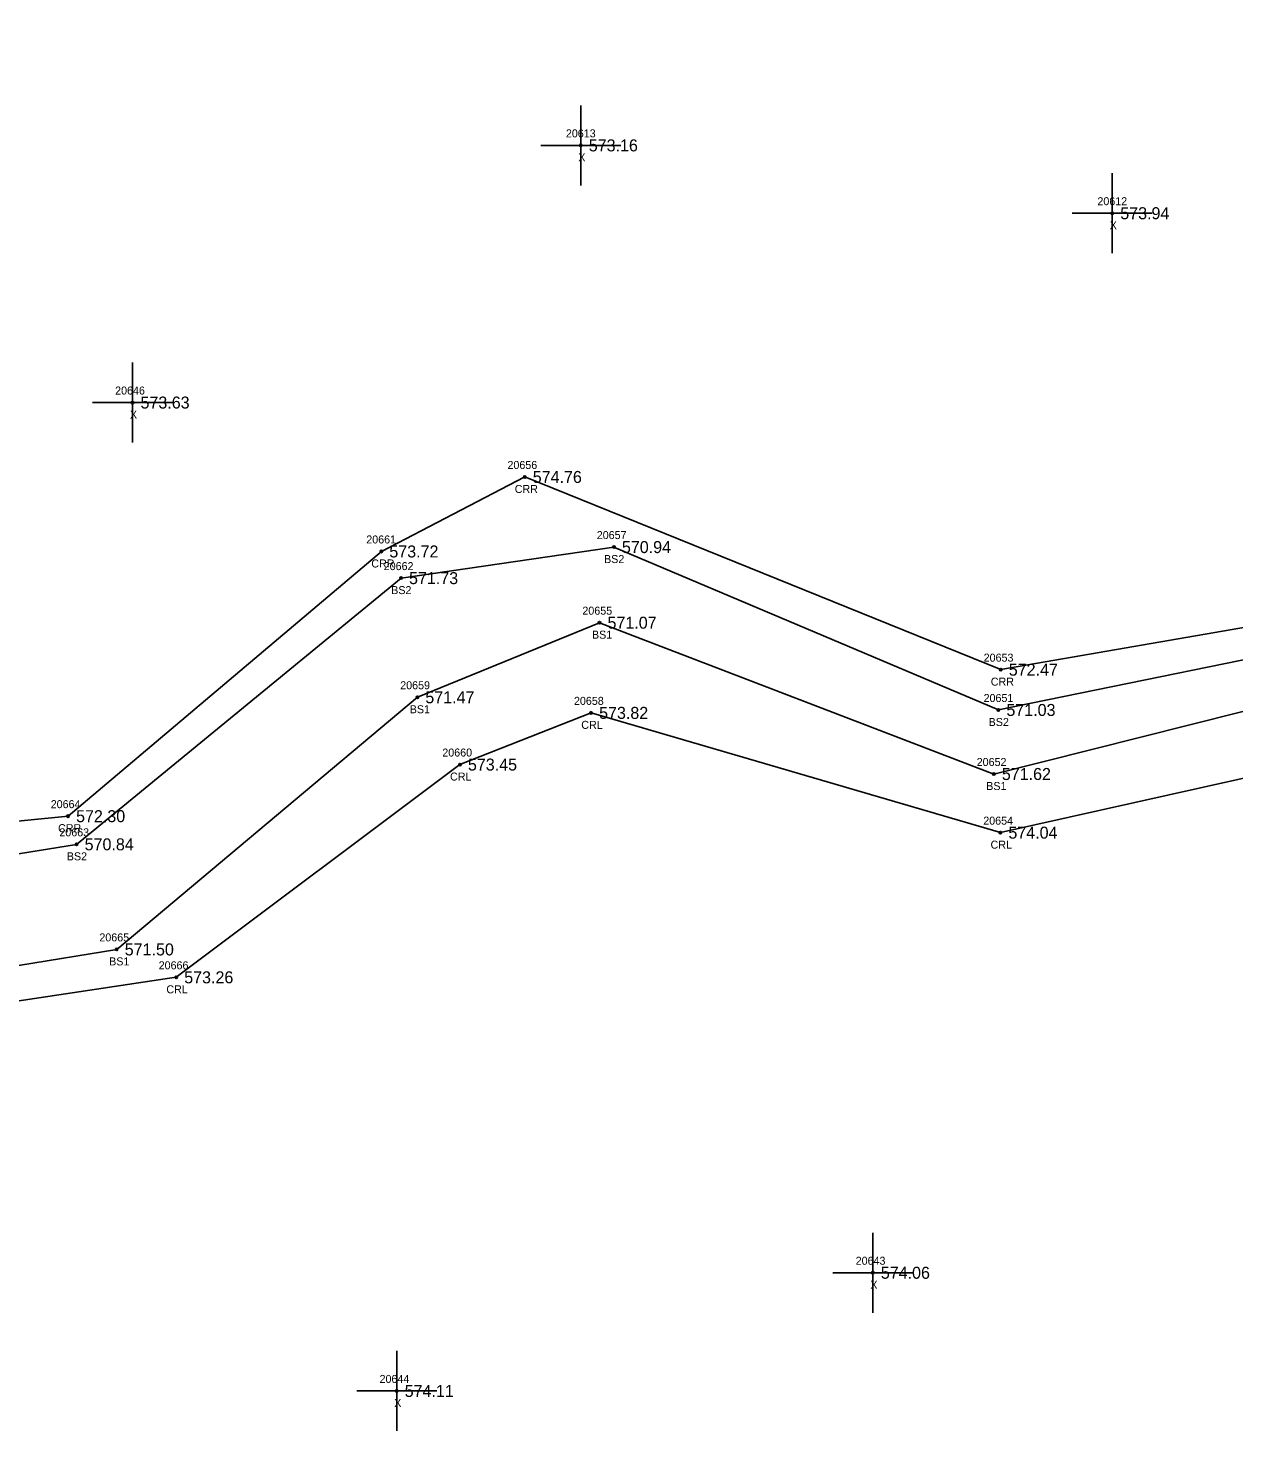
# Model space of a CAD drawing. Extents: x 1664837 to 1666270, y 987403 to 988245.
# Drawn here: x 1665162.3 to 1665313, y 987557.1 to 987732.4 of the extents above; entities that cross this region are included whole.
import ezdxf

# ---------------------------------------------------------------- set-up
doc = ezdxf.new("R2010")
doc.units = 0
for name, color, linetype in [('RD_DTM_BkLn2', 7, 'Continuous'), ('RD_DTM_BkLn_txCode', 7, 'Continuous'), ('RD_EX_H2O', 7, 'Continuous'), ('RD_EX_H2O_txCode', 7, 'Continuous'), ('RD_EX_Misc', 7, 'Continuous'), ('RD_EX_Misc_txCode', 7, 'Continuous'), ('RD_EX_TX_H2O_ELEV', 7, 'Continuous'), ('RD_EX_TX_Misc_ELEV', 7, 'Continuous'), ('RD_SMD_Locator', 7, 'Continuous')]:
    doc.layers.add(name, color=color, linetype=linetype)

msp = doc.modelspace()

# ---------------------------------------------------------------- linework, layer by layer
at = {"layer": 'RD_DTM_BkLn2'}
for points in [[(1665511.23, 987778.14), (1665500.12, 987754.08), (1665496.26, 987735.63), (1665475.45, 987718.43), (1665445.39, 987709.52), (1665428.04, 987704.31), (1665389.45, 987688.17), (1665361.39, 987673.13), (1665330.12, 987656.7), (1665283.57, 987647.17), (1665235.53, 987667.53), (1665208.93, 987663.65), (1665168.4, 987630.38), (1665122.54, 987622.98), (1665093.74, 987624.1), (1665049.09, 987603.27)], [(1665468.58, 987700.71), (1665465.66, 987702.55), (1665430.48, 987698.85), (1665398.05, 987680.55), (1665367.06, 987661.74), (1665332.15, 987651.54), (1665283, 987639.17), (1665233.73, 987658.08), (1665210.97, 987648.76), (1665173.41, 987617.25), (1665124.74, 987609.31), (1665095.75, 987609.41), (1665057.17, 987591.87)]]:
    msp.add_lwpolyline(points, dxfattribs=at)
at = {"layer": 'RD_EX_H2O'}
for points in [[(1665498.75, 987759.37), (1665497.35, 987756.86), (1665493.15, 987755.47), (1665489.09, 987748.98), (1665492.34, 987734.97), (1665472.46, 987721.68), (1665444.71, 987712.07), (1665426.39, 987705.52), (1665387.14, 987692.07), (1665353.81, 987678.17), (1665328.18, 987659.89), (1665283.87, 987652.21), (1665224.39, 987676.29), (1665206.47, 987666.98), (1665167.33, 987633.9), (1665123.23, 987629.54), (1665093.05, 987625.54), (1665046.91, 987607.08)], [(1665465.98, 987698.59), (1665465.01, 987698.79), (1665432.65, 987694.17), (1665400.81, 987677.37), (1665370.11, 987653.55), (1665334.58, 987643.2), (1665283.82, 987631.84), (1665232.68, 987646.81), (1665216.29, 987640.35), (1665180.84, 987613.76), (1665127.14, 987605.7), (1665095.77, 987606.5), (1665062.74, 987586.14)]]:
    msp.add_lwpolyline(points, dxfattribs=at)
at = {"layer": 'RD_EX_Misc'}
for p, q in [((1665231.39, 987712.73), (1665231.39, 987722.73)), ((1665226.39, 987717.73), (1665236.39, 987717.73)), ((1665297.8, 987704.25), (1665297.8, 987714.25)), ((1665292.8, 987709.25), (1665302.8, 987709.25)), ((1665175.38, 987680.59), (1665175.38, 987690.59)), ((1665170.38, 987685.59), (1665180.38, 987685.59)), ((1665267.88, 987571.84), (1665267.88, 987581.84)), ((1665262.88, 987576.84), (1665272.88, 987576.84)), ((1665208.39, 987557.07), (1665208.39, 987567.07)), ((1665203.39, 987562.07), (1665213.39, 987562.07))]:
    msp.add_line(p, q, dxfattribs=at)
at = {"layer": 'RD_SMD_Locator'}
for centre in [(1665231.39, 987717.73), (1665297.8, 987709.25), (1665175.38, 987685.59), (1665224.39, 987676.29), (1665206.47, 987666.98), (1665235.53, 987667.53), (1665208.93, 987663.65), (1665233.73, 987658.08), (1665283.87, 987652.21), (1665210.97, 987648.76), (1665283.57, 987647.17), (1665232.68, 987646.81), (1665216.29, 987640.35), (1665283, 987639.17), (1665167.33, 987633.9), (1665283.82, 987631.84), (1665168.4, 987630.38), (1665173.41, 987617.25), (1665180.84, 987613.76), (1665267.88, 987576.84), (1665208.39, 987562.07)]:
    msp.add_circle(centre, 0.15, dxfattribs=at)

# ---------------------------------------------------------------- texts
at = {"layer": 'RD_DTM_BkLn_txCode'}
for s, p in [('20657', (1665233.39, 987668.53)), ('BS2', (1665234.3, 987665.53)), ('20662', (1665206.77, 987664.65)), ('BS2', (1665207.7, 987661.65)), ('20655', (1665231.59, 987659.08)), ('BS1', (1665232.79, 987656.08)), ('20659', (1665208.83, 987649.76)), ('20651', (1665281.72, 987648.17)), ('BS1', (1665210.02, 987646.76)), ('BS2', (1665282.35, 987645.17)), ('20652', (1665280.86, 987640.17)), ('BS1', (1665282.05, 987637.17)), ('20663', (1665166.24, 987631.38)), ('BS2', (1665167.17, 987628.38)), ('20665', (1665171.24, 987618.25)), ('BS1', (1665172.46, 987615.25))]:
    msp.add_text(s, height=1, dxfattribs=at).set_placement(p)
at = {"layer": 'RD_EX_H2O_txCode'}
for s, p in [('20656', (1665222.23, 987677.29)), ('CRR', (1665223.14, 987674.29)), ('20661', (1665204.59, 987667.98)), ('CRR', (1665205.22, 987664.98)), ('20653', (1665281.73, 987653.21)), ('CRR', (1665282.62, 987650.21)), ('20658', (1665230.54, 987647.81)), ('CRL', (1665231.45, 987644.81)), ('20660', (1665214.09, 987641.35)), ('CRL', (1665215.06, 987638.35)), ('20664', (1665165.16, 987634.9)), ('20654', (1665281.68, 987632.84)), ('CRR', (1665166.08, 987631.9)), ('CRL', (1665282.59, 987629.84)), ('20666', (1665178.65, 987614.76)), ('CRL', (1665179.61, 987611.76))]:
    msp.add_text(s, height=1, dxfattribs=at).set_placement(p)
at = {"layer": 'RD_EX_Misc_txCode'}
for s, p in [('20613', (1665229.53, 987718.73)), ('X', (1665231.08, 987715.73)), ('20612', (1665295.94, 987710.25)), ('X', (1665297.48, 987707.25)), ('20646', (1665173.21, 987686.59)), ('X', (1665175.06, 987683.59)), ('20643', (1665265.74, 987577.84)), ('X', (1665267.57, 987574.84)), ('20644', (1665206.25, 987563.07)), ('X', (1665208.08, 987560.07))]:
    msp.add_text(s, height=1, dxfattribs=at).set_placement(p)
at = {"layer": 'RD_EX_TX_H2O_ELEV'}
for s, p in [('574.76', (1665225.39, 987675.54)), ('573.72', (1665207.47, 987666.23)), ('572.47', (1665284.87, 987651.46)), ('573.82', (1665233.68, 987646.06)), ('573.45', (1665217.29, 987639.6)), ('572.30', (1665168.33, 987633.15)), ('574.04', (1665284.82, 987631.09)), ('573.26', (1665181.84, 987613.01))]:
    msp.add_text(s, height=1.5, dxfattribs=at).set_placement(p)
at = {"layer": 'RD_EX_TX_Misc_ELEV'}
for s, p in [('573.16', (1665232.39, 987716.98)), ('573.94', (1665298.8, 987708.5)), ('573.63', (1665176.38, 987684.84)), ('570.94', (1665236.53, 987666.78)), ('571.73', (1665209.93, 987662.9)), ('571.07', (1665234.73, 987657.33)), ('571.47', (1665211.97, 987648.01)), ('571.03', (1665284.57, 987646.42)), ('571.62', (1665284, 987638.42)), ('570.84', (1665169.4, 987629.63)), ('571.50', (1665174.41, 987616.5)), ('574.06', (1665268.88, 987576.09)), ('574.11', (1665209.39, 987561.32))]:
    msp.add_text(s, height=1.5, dxfattribs=at).set_placement(p)

doc.saveas('drawing.dxf')
